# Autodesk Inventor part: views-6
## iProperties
Shininess: 0.0
Length Units: 11269
Angle Units: 11279
Time Units: 11290
Mass Units: 11283
Length Display Precision: 3
Angle Display Precision: 1
Compacted: True
Created: 2001-08
Part Number: views-6
Material: Cast Iron
Description: Cylinder Head
Document SubType Name: Modeling
Designer: AOTC
Density: 7.86 g/cm^3
Density: 0.0
Volumn: 0.0
Area: 0.0
PropertySet Name: Model Information
Control State: 0
Checked Out: False
Master: False
Author: AOTC
